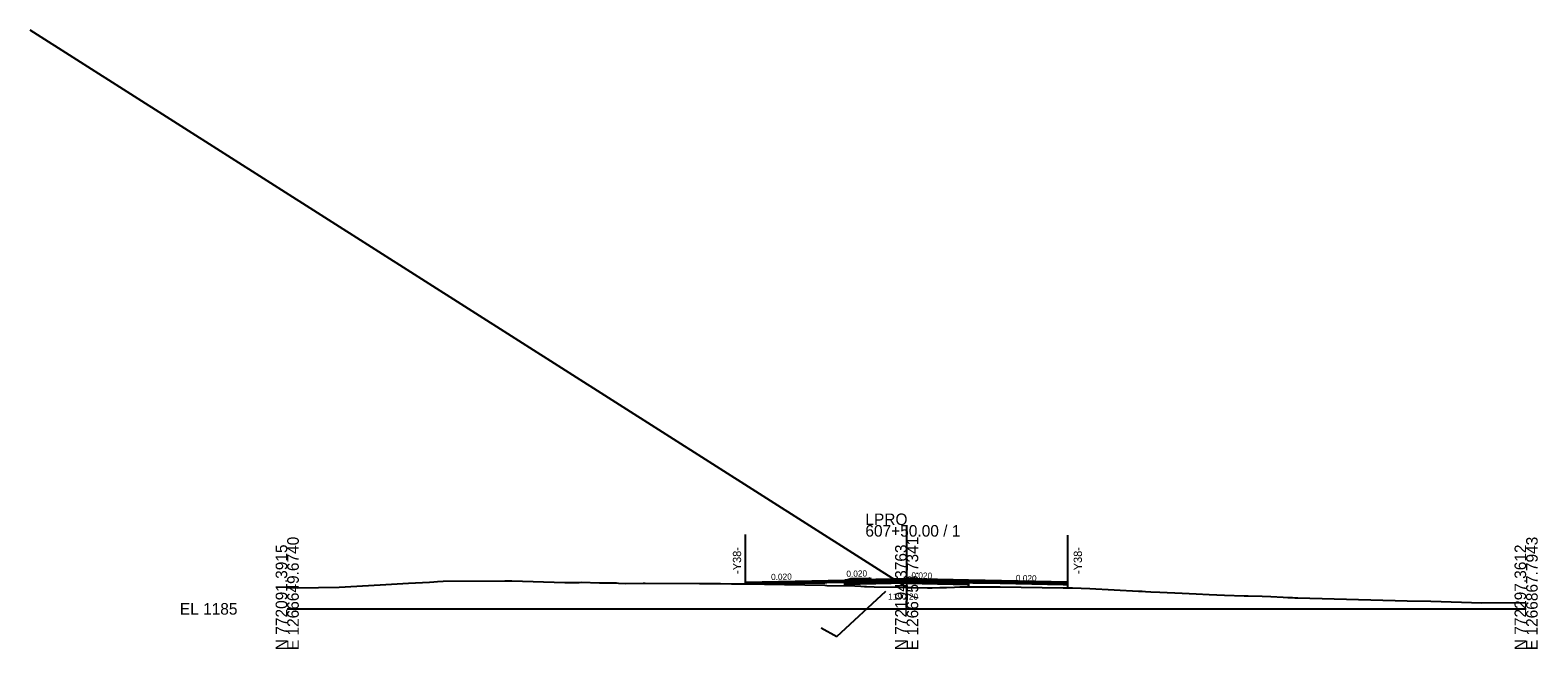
# Model space of a CAD drawing. Extents: x -3833 to 1267678, y -522 to 773248.
# Drawn here: x 937.8 to 1302.8, y 8490.3 to 8640.3 of the extents above; entities that cross this region are included whole.
import ezdxf

# ---------------------------------------------------------------- set-up
doc = ezdxf.new("R2010")
doc.units = 0
for name, color, linetype in [('Exist Cross Section Cell', 7, 'Continuous'), ('Exist XS Center Line Elevation Label', 7, 'Continuous'), ('Exist XS Ground Line', 7, 'Continuous'), ('Prop CMT DNC', 7, 'Continuous'), ('Prop CMT Pvmt Course 1', 7, 'Continuous'), ('Prop CMT Pvmt Course 2', 7, 'Continuous'), ('Prop CMT Pvmt Course 3', 7, 'Continuous'), ('Prop CMT Pvmt Course 4', 7, 'Continuous'), ('Prop CMT Shld Paved Course 1', 7, 'Continuous'), ('Prop CMT Shld Paved Course 2', 7, 'Continuous'), ('Prop CMT Subgrade Earthwork', 7, 'Continuous'), ('Prop Conc Curb and Gutter', 7, 'Continuous'), ('Prop Conc Island Cover', 7, 'Continuous'), ('Prop Corridor Mesh Bottom', 7, 'Continuous'), ('Prop XS SE Text', 7, 'Continuous'), ('Prop XS Shear Point Element', 7, 'Continuous'), ('Prop XS Shear Point Label', 7, 'Continuous'), ('Scratch_Level_1', 7, 'Continuous'), ('Scratch_Level_5', 7, 'Continuous')]:
    doc.layers.add(name, color=color, linetype=linetype)

msp = doc.modelspace()

# ---------------------------------------------------------------- linework, layer by layer
at = {"layer": 'Exist Cross Section Cell'}
for p, q in [((1150, 8500), (1150, 8520.31)), ((1000, 8500), (1150, 8500)), ((1150, 8500), (1300, 8500))]:
    msp.add_line(p, q, dxfattribs=at)
at = {"layer": 'Exist XS Ground Line'}
for p, q in [((1034.47, 8506.5), (1035.48, 8506.57)), ((1035.48, 8506.57), (1036.4, 8506.63)), ((1036.4, 8506.63), (1037.76, 8506.7)), ((1037.76, 8506.7), (1052.71, 8506.77)), ((1052.71, 8506.77), (1054.42, 8506.76)), ((1054.42, 8506.76), (1067.22, 8506.43)), ((1000, 8505.15), (1002.58, 8505.09)), ((1002.58, 8505.09), (1012.61, 8505.25)), ((1012.61, 8505.25), (1022.47, 8505.86)), ((1022.47, 8505.86), (1029.33, 8506.23)), ((1029.33, 8506.23), (1034.47, 8506.5)), ((1067.22, 8506.43), (1070.69, 8506.39)), ((1070.69, 8506.39), (1071.14, 8506.5)), ((1071.14, 8506.5), (1075.59, 8506.35)), ((1075.59, 8506.35), (1079.72, 8506.28)), ((1079.72, 8506.28), (1080.25, 8506.21)), ((1080.25, 8506.21), (1081.93, 8506.19)), ((1081.93, 8506.19), (1086.23, 8506.2)), ((1086.23, 8506.2), (1086.66, 8506.2)), ((1086.66, 8506.2), (1099.87, 8506.17)), ((1099.87, 8506.17), (1104.91, 8506.13)), ((1104.91, 8506.13), (1107.57, 8506.1)), ((1107.57, 8506.1), (1110.68, 8506.06)), ((1110.68, 8506.06), (1130.15, 8505.71)), ((1130.15, 8505.71), (1130.67, 8505.7)), ((1130.67, 8505.7), (1137.48, 8505.58)), ((1137.48, 8505.58), (1138.93, 8505.49)), ((1138.93, 8505.49), (1139.8, 8505.44)), ((1139.8, 8505.44), (1140.3, 8505.42)), ((1140.3, 8505.42), (1142.16, 8505.37)), ((1142.16, 8505.37), (1148.24, 8505.24)), ((1148.24, 8505.24), (1150, 8505.2)), ((1150, 8505.2), (1151.37, 8505.17)), ((1151.37, 8505.17), (1155.05, 8505.1)), ((1155.05, 8505.1), (1156.21, 8505.11)), ((1156.21, 8505.11), (1158.03, 8505.15)), ((1158.03, 8505.15), (1159.67, 8505.2)), ((1159.67, 8505.2), (1161.58, 8505.29)), ((1161.58, 8505.29), (1162.88, 8505.33)), ((1162.88, 8505.33), (1166.03, 8505.38)), ((1166.03, 8505.38), (1172.62, 8505.34)), ((1172.62, 8505.34), (1187.88, 8505.13)), ((1187.88, 8505.13), (1190.16, 8505.1)), ((1190.16, 8505.1), (1194.34, 8504.92)), ((1194.34, 8504.92), (1206.16, 8504.33)), ((1206.16, 8504.33), (1207.02, 8504.28)), ((1207.02, 8504.28), (1207.83, 8504.24)), ((1207.83, 8504.24), (1209.14, 8504.15)), ((1209.14, 8504.15), (1211.31, 8504.03)), ((1211.31, 8504.03), (1216.71, 8503.79)), ((1216.71, 8503.79), (1220.1, 8503.61)), ((1220.1, 8503.61), (1223.29, 8503.49)), ((1223.29, 8503.49), (1226.95, 8503.32)), ((1226.95, 8503.32), (1231.75, 8503.16)), ((1231.75, 8503.16), (1232.66, 8503.13)), ((1232.66, 8503.13), (1236.06, 8503.04)), ((1236.06, 8503.04), (1238.15, 8503)), ((1238.15, 8503), (1241.14, 8502.83)), ((1241.14, 8502.83), (1242.28, 8502.78)), ((1242.28, 8502.78), (1242.91, 8502.76)), ((1242.91, 8502.76), (1243.39, 8502.74)), ((1243.39, 8502.74), (1243.99, 8502.68)), ((1243.99, 8502.68), (1244.73, 8502.68)), ((1244.73, 8502.68), (1271.22, 8501.97)), ((1271.22, 8501.97), (1276.95, 8501.85)), ((1276.95, 8501.85), (1284.34, 8501.66)), ((1284.34, 8501.66), (1289.16, 8501.46)), ((1289.16, 8501.46), (1300, 8501.55))]:
    msp.add_line(p, q, dxfattribs=at)
at = {"layer": 'Prop CMT Pvmt Course 1'}
for p, q in [((1111, 8506.47), (1135, 8506.95)), ((1135, 8506.7), (1111, 8506.22)), ((1135, 8506.95), (1135.75, 8506.96)), ((1135, 8506.7), (1135, 8506.95)), ((1135, 8506.95), (1135, 8506.95)), ((1135, 8506.95), (1135, 8506.95)), ((1135, 8506.95), (1135, 8506.95)), ((1135, 8506.95), (1135, 8506.7)), ((1135.75, 8506.71), (1135, 8506.7)), ((1135, 8506.7), (1135, 8506.7)), ((1135.75, 8506.96), (1135.75, 8506.96)), ((1135.75, 8506.96), (1135.75, 8506.96)), ((1135.75, 8506.96), (1135.75, 8506.71)), ((1135.75, 8506.71), (1135.75, 8506.71)), ((1141.43, 8506.03), (1141.43, 8507.07)), ((1142.2, 8507.09), (1142.2, 8507.08)), ((1142.2, 8507.08), (1142.2, 8506.05)), ((1189, 8506.47), (1165, 8506.95)), ((1165, 8506.95), (1165, 8506.95)), ((1165, 8506.95), (1165, 8506.95)), ((1165, 8506.95), (1165, 8506.7)), ((1165, 8506.7), (1189, 8506.22)), ((1165, 8506.7), (1165, 8506.7)), ((1111, 8506.47), (1111, 8506.47)), ((1189, 8506.47), (1189, 8506.47))]:
    msp.add_line(p, q, dxfattribs=at)
at = {"layer": 'Prop CMT Pvmt Course 2'}
for p, q in [((1150, 8507), (1135, 8506.7)), ((1135, 8506.7), (1135.75, 8506.71)), ((1135, 8506.45), (1135, 8506.7)), ((1135, 8506.7), (1135, 8506.7)), ((1135, 8506.7), (1135, 8506.7)), ((1135, 8506.7), (1135, 8506.37)), ((1135, 8506.36), (1150, 8506.67)), ((1135.75, 8506.71), (1135.75, 8506.71)), ((1135.75, 8506.71), (1135.75, 8506.71)), ((1135.75, 8506.71), (1135.75, 8506.46)), ((1165, 8506.7), (1150, 8507)), ((1150, 8507), (1150, 8507)), ((1150, 8507), (1150, 8507)), ((1150, 8506.67), (1150, 8506.67)), ((1150, 8506.67), (1150, 8506.67)), ((1150, 8506.67), (1165, 8506.36)), ((1165, 8506.36), (1165, 8506.7)), ((1165, 8506.7), (1165, 8506.7)), ((1135, 8506.37), (1135, 8506.36)), ((1135.75, 8506.46), (1135.75, 8506.46)), ((1165, 8506.36), (1165, 8506.36))]:
    msp.add_line(p, q, dxfattribs=at)
at = {"layer": 'Prop CMT Pvmt Course 3'}
for p, q in [((1135, 8506.07), (1135, 8506.45)), ((1135, 8506.45), (1135, 8506.45)), ((1135.75, 8506.46), (1135.75, 8506.46)), ((1135.75, 8506.46), (1135.75, 8506.46)), ((1135.75, 8506.46), (1135.75, 8506.09)), ((1135.75, 8506.09), (1135.75, 8506.09))]:
    msp.add_line(p, q, dxfattribs=at)
at = {"layer": 'Prop CMT Pvmt Course 4'}
for p, q in [((1135, 8506.36), (1150, 8506.67)), ((1150, 8506.67), (1150, 8506.67)), ((1150, 8506.67), (1150, 8506.67)), ((1150, 8506.67), (1165, 8506.36)), ((1135, 8505.62), (1135, 8506.37)), ((1135, 8506.37), (1135, 8506.37)), ((1135, 8506.37), (1135, 8506.36)), ((1135, 8505.62), (1135, 8506.07)), ((1135, 8506.07), (1135, 8506.07)), ((1135.75, 8506.09), (1135.75, 8506.09)), ((1135.75, 8506.09), (1135.75, 8506.09)), ((1135.75, 8506.09), (1135.75, 8505.92)), ((1135.75, 8505.59), (1135.75, 8505.59)), ((1149.99, 8506.21), (1165, 8505.9)), ((1165, 8506.36), (1165, 8506.36)), ((1165, 8506.36), (1165, 8506.36)), ((1165, 8506.36), (1165, 8505.37)), ((1165, 8505.53), (1165, 8505.53))]:
    msp.add_line(p, q, dxfattribs=at)
at = {"layer": 'Prop CMT Shld Paved Course 1'}
for p, q in [((1150, 8507.25), (1135, 8506.95)), ((1135, 8506.7), (1150, 8507)), ((1135, 8506.95), (1135, 8506.95)), ((1135, 8506.95), (1135, 8506.7)), ((1165, 8506.95), (1150, 8507.25)), ((1150, 8507.25), (1150, 8507.25)), ((1150, 8507.25), (1150, 8507.25)), ((1150, 8507), (1150, 8507)), ((1150, 8507), (1150, 8507)), ((1150, 8507), (1165, 8506.7)), ((1165, 8506.7), (1165, 8506.95)), ((1165, 8506.95), (1165, 8506.95))]:
    msp.add_line(p, q, dxfattribs=at)
at = {"layer": 'Prop CMT Shld Paved Course 2'}
for p, q in [((1111, 8506.22), (1130.15, 8506.6)), ((1130.15, 8506.6), (1130.67, 8506.61)), ((1130.15, 8506.6), (1130.15, 8506.6)), ((1130.67, 8506.61), (1135, 8506.7)), ((1135, 8506.7), (1135, 8506.7)), ((1135, 8506.7), (1135, 8506.36)), ((1166.03, 8506.67), (1165, 8506.7)), ((1165, 8506.7), (1165, 8506.7)), ((1165, 8506.7), (1165, 8506.7)), ((1165, 8506.7), (1165, 8506.36)), ((1172.62, 8506.54), (1166.03, 8506.67)), ((1111, 8506.22), (1111, 8506.22)), ((1111, 8506.22), (1111, 8506.22)), ((1111, 8506.22), (1111, 8506.22)), ((1115.61, 8505.97), (1111, 8506.06)), ((1111, 8506.06), (1111, 8506.06)), ((1130.15, 8506.27), (1115.61, 8505.97)), ((1115.61, 8505.97), (1115.61, 8505.97)), ((1115.61, 8505.97), (1115.61, 8505.97)), ((1130.67, 8506.28), (1130.15, 8506.27)), ((1130.15, 8506.27), (1130.15, 8506.27)), ((1135, 8506.36), (1130.67, 8506.28)), ((1165, 8506.36), (1165, 8506.36)), ((1165, 8506.36), (1166.03, 8506.34)), ((1166.03, 8506.34), (1172.62, 8506.21)), ((1187.88, 8506.24), (1172.62, 8506.54)), ((1172.62, 8506.54), (1172.62, 8506.54)), ((1172.62, 8506.54), (1172.62, 8506.54)), ((1172.62, 8506.21), (1172.62, 8506.21)), ((1172.62, 8506.21), (1172.62, 8506.21)), ((1172.62, 8506.21), (1187.88, 8505.9)), ((1189, 8506.22), (1187.88, 8506.24)), ((1187.88, 8506.24), (1187.88, 8506.24)), ((1187.88, 8505.9), (1187.88, 8505.9)), ((1187.88, 8505.9), (1189, 8505.88)), ((1189, 8506.22), (1189, 8506.22))]:
    msp.add_line(p, q, dxfattribs=at)
at = {"layer": 'Prop CMT Subgrade Earthwork'}
for p, q in [((1150.01, 8506.21), (1135, 8505.9)), ((1135, 8505.62), (1135, 8505.9)), ((1165, 8505.9), (1149.99, 8506.21)), ((1165, 8505.37), (1165, 8505.9))]:
    msp.add_line(p, q, dxfattribs=at)
at = {"layer": 'Prop Conc Curb and Gutter'}
for p, q in [((1135.75, 8506.96), (1135.76, 8507.13)), ((1135.75, 8506.96), (1135.75, 8506.96)), ((1135.75, 8506.96), (1135.75, 8506.96)), ((1135.75, 8506.96), (1135.75, 8506.84)), ((1135.75, 8506.84), (1137.96, 8506.89)), ((1135.76, 8507.13), (1136.51, 8507.38)), ((1135.76, 8507.13), (1135.76, 8507.13)), ((1136.51, 8507.38), (1140.82, 8507.47)), ((1136.51, 8507.38), (1136.51, 8507.38)), ((1137.96, 8506.89), (1140.43, 8506.94)), ((1140.43, 8506.94), (1141.43, 8506.98)), ((1141.42, 8507.27), (1140.82, 8507.47)), ((1141.42, 8507.26), (1141.42, 8507.27)), ((1141.43, 8507.11), (1141.42, 8507.26)), ((1141.43, 8507.1), (1141.43, 8507.11)), ((1141.43, 8506.98), (1141.43, 8507.1))]:
    msp.add_line(p, q, dxfattribs=at)
at = {"layer": 'Prop Conc Island Cover'}
msp.add_line((1136.51, 8507.38), (1136.51, 8507.38), dxfattribs=at)
msp.add_line((1136.51, 8507.38), (1136.51, 8507.38), dxfattribs=at)
at = {"layer": 'Prop Corridor Mesh Bottom'}
for p, q in [((1135, 8506.95), (1135, 8506.7)), ((1165, 8506.95), (1165, 8506.7))]:
    msp.add_line(p, q, dxfattribs=at)
at = {"layer": 'Prop XS Shear Point Element'}
for p, q in [((1111, 8506.06), (1111, 8518.03)), ((1189, 8505.12), (1189, 8517.85))]:
    msp.add_line(p, q, dxfattribs=at)
at = {"layer": 'Scratch_Level_1'}
msp.add_line((1150, 8505.2), (937.75, 8640.26), dxfattribs=at)
at = {"layer": 'Scratch_Level_5'}
for p, q in [((1133.08, 8493.29), (1144.94, 8504.32)), ((1129.3, 8495.4), (1133.08, 8493.29))]:
    msp.add_line(p, q, dxfattribs=at)

# ---------------------------------------------------------------- texts
at = {"layer": 'Exist Cross Section Cell'}
for s, p in [('LPRO', (1140, 8520.31)), ('607+50.00 / 1', (1140, 8517.51)), ('EL 1185', (974, 8498.6))]:
    msp.add_text(s, height=2.8, dxfattribs=at).set_placement(p)
for s, p in [('N 772091.3915', (1000, 8490)), ('E 1266649.6740', (1002.8, 8490)), ('N 772194.3763', (1150, 8490)), ('E 1266758.7341', (1152.8, 8490)), ('N 772297.3612', (1300, 8490)), ('E 1266867.7943', (1302.8, 8490))]:
    msp.add_text(s, height=2.8, rotation=90, dxfattribs=at).set_placement(p)
at = {"layer": 'Exist XS Center Line Elevation Label'}
msp.add_text('1190.20', height=1.5, dxfattribs=at).set_placement((1145.52, 8502.22))
at = {"layer": 'Prop CMT DNC'}
for p in [(1135, 8506.95), (1135, 8506.95), (1150, 8507.25), (1165, 8506.95), (1165, 8506.95), (1111, 8506.47), (1189, 8506.47), (1189, 8506.47)]:
    msp.add_text('X', height=0.00025, dxfattribs=at).set_placement(p)
at = {"layer": 'Prop XS SE Text'}
for rotation, p in [(1.397, (1117.18, 8506.97)), (1.2964, (1135.42, 8507.74)), (358.8542, (1151.14, 8507.37)), (358.8542, (1176.43, 8506.75))]:
    msp.add_text('0.020', height=1.5, rotation=rotation, dxfattribs=at).set_placement(p)
at = {"layer": 'Prop XS Shear Point Label'}
for p in [(1109.91, 8508.45), (1192.44, 8508.45)]:
    msp.add_text('-Y38-', height=2, rotation=90, dxfattribs=at).set_placement(p)

doc.saveas('drawing.dxf')
